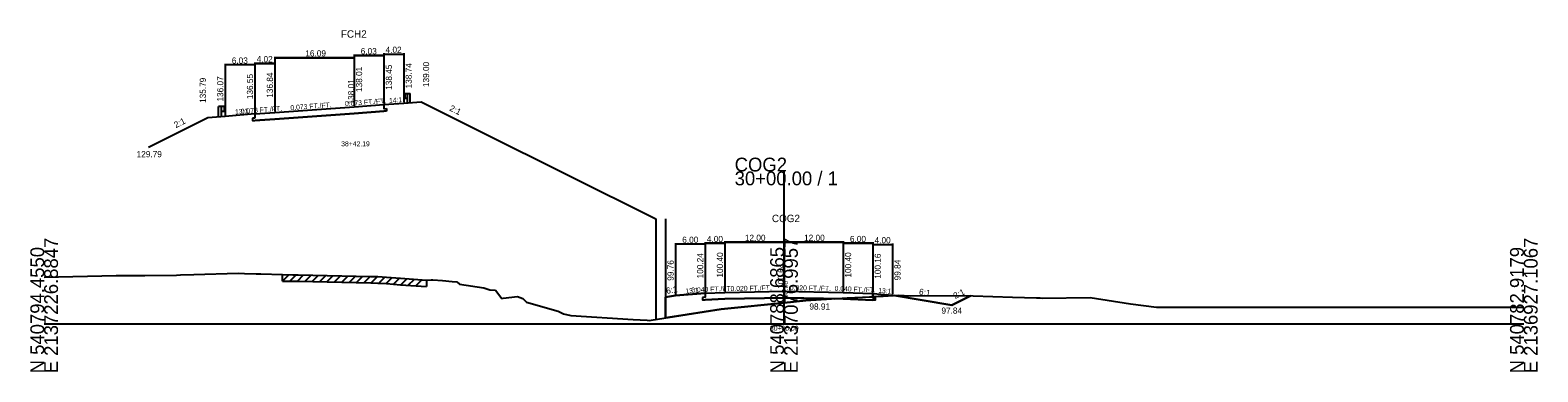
# Model space of a CAD drawing. Extents: x -13397 to 2303, y -10 to 39059.
# Drawn here: x 997.2 to 1302.8, y -9.7 to 59.5 of the extents above; entities that cross this region are included whole.
import ezdxf

# ---------------------------------------------------------------- set-up
doc = ezdxf.new("R2010")
doc.units = 0
for name, color, linetype in [('Level 20', 7, 'Continuous'), ('Level 5', 7, 'Continuous'), ('Level 53', 7, 'Continuous'), ('Level 54', 7, 'Continuous'), ('Level 55', 7, 'Continuous'), ('Level 7', 7, 'Continuous'), ('RD_GPK_XS_Cell', 7, 'Continuous'), ('RD_XS_EwShp', 7, 'Continuous'), ('RD_XS_ExGround', 7, 'Continuous'), ('RD_XS_ExPaveRet', 7, 'Continuous'), ('RD_XS_MedBWall', 7, 'Continuous'), ('RD_XS_Pave', 7, 'Continuous'), ('RD_XS_TX_Baseline', 7, 'Continuous'), ('RD_XS_TX_Elev_EX', 7, 'Continuous'), ('RD_XS_TX_Elev_PR', 7, 'Continuous'), ('RD_XS_TX_Station', 7, 'Continuous')]:
    doc.layers.add(name, color=color, linetype=linetype)

msp = doc.modelspace()

# ---------------------------------------------------------------- linework, layer by layer
at = {"layer": 'Level 20'}
for p, q in [((1036.7, 52.7), (1036.7, 42.27)), ((1042.74, 52.5), (1036.7, 52.5)), ((1042.74, 52.99), (1042.74, 42.75)), ((1042.74, 52.99), (1042.74, 42.75)), ((1042.74, 52.99), (1042.74, 42.75)), ((1042.74, 52.79), (1046.76, 52.79)), ((1042.74, 52.79), (1046.76, 52.79)), ((1046.76, 52.79), (1042.74, 52.79)), ((1042.74, 52.7), (1042.74, 42.75)), ((1046.76, 54.16), (1046.76, 43.04)), ((1046.76, 54.16), (1046.76, 43.04)), ((1046.76, 54.16), (1046.76, 43.04)), ((1046.76, 54.16), (1046.76, 43.04)), ((1046.76, 53.96), (1062.84, 53.96)), ((1046.76, 53.96), (1062.84, 53.96)), ((1062.84, 53.96), (1046.76, 53.96)), ((1062.84, 53.96), (1046.76, 53.96)), ((1046.76, 52.99), (1046.76, 43.04)), ((1046.76, 52.99), (1046.76, 43.04)), ((1046.76, 52.99), (1046.76, 43.04)), ((1062.84, 54.6), (1062.84, 44.21)), ((1062.84, 54.6), (1062.84, 44.21)), ((1062.84, 54.6), (1062.84, 44.21)), ((1062.84, 54.4), (1068.88, 54.4)), ((1068.88, 54.4), (1062.84, 54.4)), ((1068.88, 54.4), (1062.84, 54.4)), ((1062.84, 54.16), (1062.84, 44.21)), ((1062.84, 54.16), (1062.84, 44.21)), ((1062.84, 54.16), (1062.84, 44.21)), ((1062.84, 54.16), (1062.84, 44.21)), ((1068.88, 54.89), (1068.88, 44.65)), ((1068.88, 54.69), (1072.9, 54.69)), ((1068.88, 54.6), (1068.88, 44.65)), ((1068.88, 54.6), (1068.88, 44.65)), ((1068.88, 54.6), (1068.88, 44.65)), ((1072.9, 54.89), (1072.9, 44.94)), ((1072.92, 46.56), (1073.03, 46.65)), ((1072.92, 46.46), (1073.03, 46.37)), ((1072.92, 46.03), (1073.03, 46.12)), ((1072.92, 45.93), (1073.03, 45.84)), ((1073.05, 46.66), (1073.12, 46.67)), ((1073.05, 46.32), (1073.05, 46.17)), ((1073.12, 46.73), (1073.12, 45.76)), ((1073.12, 46.73), (1073.68, 46.73)), ((1073.68, 44.74), (1073.68, 46.73)), ((1073.68, 46.73), (1074.23, 46.73)), ((1074.23, 44.74), (1074.23, 46.73)), ((1035.36, 42.07), (1035.36, 44.06)), ((1035.92, 44.06), (1035.36, 44.06)), ((1035.92, 42.07), (1035.92, 44.06)), ((1036.48, 44.06), (1035.92, 44.06)), ((1036.48, 43.08), (1035.92, 43.08)), ((1036.48, 44.06), (1036.48, 43.08)), ((1036.55, 43.98), (1036.48, 43.99)), ((1036.55, 43.16), (1036.48, 43.14)), ((1036.55, 43.65), (1036.55, 43.49)), ((1036.68, 43.88), (1036.57, 43.98)), ((1036.68, 43.78), (1036.57, 43.69)), ((1036.68, 43.35), (1036.57, 43.45)), ((1036.68, 43.25), (1036.57, 43.16)), ((1042.74, 42.55), (1046.76, 42.84)), ((1046.76, 42.84), (1062.84, 44.01)), ((1062.84, 44.01), (1068.88, 44.45)), ((1068.88, 43.12), (1062.84, 42.68)), ((1062.84, 42.68), (1068.88, 43.12)), ((1062.84, 42.68), (1068.88, 43.12)), ((1068.88, 44.45), (1072.9, 44.74)), ((1068.88, 44.45), (1068.88, 43.62)), ((1068.88, 43.62), (1069.38, 43.65)), ((1069.38, 43.15), (1068.88, 43.12)), ((1069.38, 43.65), (1069.38, 43.15)), ((1072.9, 44.74), (1076.42, 45)), ((1073.05, 45.83), (1073.12, 45.82)), ((1073.12, 45.76), (1073.68, 45.76)), ((1076.42, 45), (1088.48, 39)), ((1033.18, 41.79), (1021.12, 35.79)), ((1036.7, 42.07), (1033.18, 41.79)), ((1042.74, 42.55), (1036.7, 42.07)), ((1042.74, 41.71), (1042.23, 41.68)), ((1042.23, 41.68), (1042.23, 41.18)), ((1042.23, 41.18), (1042.74, 41.21)), ((1042.74, 42.55), (1042.74, 41.71)), ((1046.76, 41.51), (1042.74, 41.21)), ((1046.76, 41.51), (1042.74, 41.21)), ((1042.74, 41.21), (1046.76, 41.51)), ((1062.84, 42.68), (1046.76, 41.51)), ((1062.84, 42.68), (1046.76, 41.51)), ((1046.76, 41.51), (1062.84, 42.68)), ((1046.76, 41.51), (1062.84, 42.68)), ((1088.48, 39), (1124, 21.33))]:
    msp.add_line(p, q, dxfattribs=at)
for centre, radius, start, end in [((1072.96, 46.51), 0.0651, 129.0336, 230.9663), ((1072.96, 45.98), 0.0651, 129.0336, 230.9663), ((1072.99, 46.17), 0.0651, 302.9895, 0), ((1073.05, 46.63), 0.026, 90, 129.0505), ((1072.99, 46.32), 0.0651, 0, 45), ((1036.55, 43.96), 0.026, 50.9495, 90), ((1036.61, 43.65), 0.0651, 135, 180), ((1036.61, 43.49), 0.0651, 180, 237.0105), ((1036.55, 43.18), 0.026, 270, 309.0504), ((1036.64, 43.83), 0.0651, 309.0337, 50.9664), ((1036.64, 43.3), 0.0651, 309.0337, 50.9664), ((1073.05, 45.86), 0.026, 230.9496, 270)]:
    msp.add_arc(centre, radius, start, end, dxfattribs=at)
at = {"layer": 'Level 5'}
for p, q in [((1134, 6.24), (1134, 5.41)), ((1168, 6.16), (1168, 5.33)), ((1134, 5.41), (1133.5, 5.39)), ((1133.5, 5.39), (1133.5, 4.89)), ((1133.5, 4.89), (1134, 4.91)), ((1138, 5.07), (1134, 4.91)), ((1138, 5.07), (1134, 4.91)), ((1138, 5.07), (1134, 4.91)), ((1134, 4.91), (1138, 5.07)), ((1150, 5.31), (1138, 5.07)), ((1150, 5.31), (1138, 5.07)), ((1150, 5.31), (1138, 5.07)), ((1138, 5.07), (1150, 5.31)), ((1138, 5.07), (1150, 5.31)), ((1162, 5.07), (1150, 5.31)), ((1162, 5.07), (1150, 5.31)), ((1150, 5.31), (1162, 5.07)), ((1150, 5.31), (1162, 5.07)), ((1150, 5.31), (1162, 5.07)), ((1168, 4.83), (1162, 5.07)), ((1162, 5.07), (1168, 4.83)), ((1162, 5.07), (1168, 4.83)), ((1162, 5.07), (1168, 4.83)), ((1168, 5.33), (1168.5, 5.31)), ((1168.5, 4.81), (1168, 4.83)), ((1168.5, 5.31), (1168.5, 4.81))]:
    msp.add_line(p, q, dxfattribs=at)
at = {"layer": 'Level 54'}
for p, q in [((1128, 16.39), (1128, 5.96)), ((1134, 16.19), (1128, 16.19)), ((1134, 16.55), (1134, 6.44)), ((1134, 16.55), (1134, 6.44)), ((1134, 16.55), (1134, 6.44)), ((1134, 16.55), (1134, 6.44)), ((1134, 16.39), (1134, 6.44)), ((1134, 16.35), (1138, 16.35)), ((1134, 16.35), (1138, 16.35)), ((1134, 16.35), (1138, 16.35)), ((1138, 16.35), (1134, 16.35)), ((1138, 16.79), (1138, 6.6)), ((1138, 16.79), (1138, 6.6)), ((1138, 16.79), (1138, 6.6)), ((1138, 16.79), (1138, 6.6)), ((1138, 16.79), (1138, 6.6)), ((1138, 16.59), (1150, 16.59)), ((1138, 16.59), (1150, 16.59)), ((1138, 16.59), (1150, 16.59)), ((1150, 16.59), (1138, 16.59)), ((1150, 16.59), (1138, 16.59)), ((1138, 16.55), (1138, 6.6)), ((1138, 16.55), (1138, 6.6)), ((1138, 16.55), (1138, 6.6)), ((1138, 16.55), (1138, 6.6)), ((1150, 16.79), (1150, 6.84)), ((1150, 16.79), (1150, 6.84)), ((1150, 16.79), (1150, 6.84)), ((1150, 16.79), (1150, 6.84)), ((1150, 16.79), (1150, 6.84)), ((1150, 16.79), (1150, 6.84)), ((1150, 16.79), (1150, 6.84)), ((1150, 16.79), (1150, 6.84)), ((1150, 16.79), (1150, 6.84)), ((1150, 16.79), (1150, 6.84)), ((1150, 16.59), (1162, 16.59)), ((1150, 16.59), (1162, 16.59)), ((1162, 16.59), (1150, 16.59)), ((1162, 16.59), (1150, 16.59)), ((1162, 16.59), (1150, 16.59)), ((1162, 16.79), (1162, 6.6)), ((1162, 16.79), (1162, 6.6)), ((1162, 16.79), (1162, 6.6)), ((1162, 16.79), (1162, 6.6)), ((1162, 16.79), (1162, 6.6)), ((1162, 16.55), (1162, 6.6)), ((1162, 16.55), (1162, 6.6)), ((1162, 16.55), (1162, 6.6)), ((1162, 16.55), (1162, 6.6)), ((1162, 16.35), (1168, 16.35)), ((1168, 16.35), (1162, 16.35)), ((1168, 16.35), (1162, 16.35)), ((1168, 16.35), (1162, 16.35)), ((1168, 16.55), (1168, 6.36)), ((1168, 16.55), (1168, 6.36)), ((1168, 16.55), (1168, 6.36)), ((1168, 16.55), (1168, 6.36)), ((1168, 16.31), (1168, 6.36)), ((1168, 16.11), (1172, 16.11)), ((1172, 16.31), (1172, 6.04))]:
    msp.add_line(p, q, dxfattribs=at)
at = {"layer": 'Level 7'}
for p, q in [((1134, 6.24), (1128, 5.76)), ((1168, 6.16), (1172, 5.84)), ((1128, 5.76), (1126, 5.43)), ((1126, 5.43), (1126, 1.24)), ((1172, 5.84), (1184, 3.84)), ((1184, 3.84), (1187.78, 5.73))]:
    msp.add_line(p, q, dxfattribs=at)
at = {"layer": 'RD_GPK_XS_Cell'}
for p, q in [((1150, 0), (1150, 30.9)), ((1000, 0), (1150, 0)), ((1150, 0), (1300, 0))]:
    msp.add_line(p, q, dxfattribs=at)
at = {"layer": 'RD_XS_EwShp'}
for points in [[(1133.5, 5.39), (1133.5, 4.89), (1134, 4.91), (1138, 5.07), (1150, 5.31), (1160.14, 5.1), (1154.45, 4.75), (1150.03, 4.28), (1137.96, 3.04), (1137.24, 2.98), (1130.35, 1.93), (1126, 1.24), (1126, 5.43), (1128, 5.76), (1134, 6.24), (1134, 5.41)], [(1168, 6.16), (1172, 5.84), (1172.43, 5.77), (1170.08, 5.61), (1168, 5.53)], [(1162, 5.07), (1160.14, 5.1), (1162.81, 5.27), (1165.93, 5.45), (1168, 5.53), (1168, 5.33), (1168.5, 5.31), (1168.5, 4.81), (1168, 4.83)], [(1172.43, 5.77), (1173.22, 5.82), (1175.59, 5.73), (1186.32, 5.77), (1187.78, 5.73), (1184, 3.84)]]:
    msp.add_lwpolyline(points, close=True, dxfattribs=at)
at = {"layer": 'RD_XS_ExGround'}
for p, q in [((1000, 9.46), (1014.6, 9.84)), ((1014.6, 9.84), (1020.44, 9.8)), ((1020.44, 9.8), (1026.83, 9.91)), ((1026.83, 9.91), (1027.64, 9.93)), ((1027.64, 9.93), (1030.34, 10.02)), ((1030.34, 10.02), (1039.33, 10.3)), ((1039.33, 10.3), (1040.59, 10.23)), ((1040.59, 10.23), (1042.99, 10.18)), ((1042.99, 10.18), (1043.9, 10.16)), ((1043.9, 10.16), (1048.33, 10.01)), ((1048.33, 10.01), (1050.43, 9.98)), ((1050.43, 9.98), (1051.53, 9.95)), ((1051.53, 9.95), (1066.22, 9.63)), ((1066.22, 9.63), (1067.68, 9.59)), ((1067.68, 9.59), (1069.39, 9.49)), ((1069.39, 9.49), (1072.24, 9.26)), ((1072.24, 9.26), (1077.52, 8.9)), ((1077.52, 8.9), (1078.47, 8.97)), ((1078.47, 8.97), (1078.8, 8.96)), ((1078.8, 8.96), (1080.76, 8.83)), ((1080.76, 8.83), (1082.71, 8.62)), ((1082.71, 8.62), (1083.68, 8.53)), ((1083.68, 8.53), (1084.18, 8.09)), ((1084.18, 8.09), (1089.14, 7.34)), ((1089.14, 7.34), (1090.36, 6.93)), ((1090.36, 6.93), (1091.51, 6.83)), ((1091.51, 6.83), (1092.77, 5.19)), ((1092.77, 5.19), (1093.09, 5.23)), ((1093.09, 5.23), (1095.97, 5.56)), ((1095.97, 5.56), (1097.02, 5.15)), ((1097.02, 5.15), (1097.8, 4.44)), ((1097.8, 4.44), (1104.19, 2.62)), ((1137.96, 3.04), (1150.03, 4.28)), ((1150.03, 4.28), (1154.45, 4.75)), ((1154.45, 4.75), (1162.81, 5.27)), ((1162.81, 5.27), (1165.93, 5.45)), ((1165.93, 5.45), (1170.08, 5.61)), ((1170.08, 5.61), (1173.22, 5.82)), ((1173.22, 5.82), (1175.59, 5.73)), ((1175.59, 5.73), (1186.32, 5.77)), ((1186.32, 5.77), (1188.37, 5.72)), ((1188.37, 5.72), (1196.34, 5.46)), ((1196.34, 5.46), (1201.16, 5.28)), ((1201.16, 5.28), (1201.92, 5.29)), ((1201.92, 5.29), (1202.41, 5.26)), ((1202.41, 5.26), (1212.05, 5.35)), ((1212.05, 5.35), (1220.24, 4.07)), ((1220.24, 4.07), (1225.55, 3.44)), ((1225.55, 3.44), (1231.98, 3.44)), ((1231.98, 3.44), (1300, 3.44)), ((1104.19, 2.62), (1105.3, 2.03)), ((1105.3, 2.03), (1106.78, 1.72)), ((1106.78, 1.72), (1119.44, 0.93)), ((1119.44, 0.93), (1122.29, 0.76)), ((1122.29, 0.76), (1122.66, 0.73)), ((1122.66, 0.73), (1123.07, 0.78)), ((1123.07, 0.78), (1130.35, 1.93)), ((1130.35, 1.93), (1137.24, 2.98)), ((1137.24, 2.98), (1137.96, 3.04))]:
    msp.add_line(p, q, dxfattribs=at)
at = {"layer": 'RD_XS_ExPaveRet'}
for p, q in [((1048.33, 8.71), (1048.33, 10.01)), ((1048.33, 8.71), (1049.62, 9.99)), ((1049.83, 8.69), (1051.11, 9.96)), ((1051.33, 8.66), (1052.61, 9.93)), ((1052.83, 8.62), (1054.11, 9.9)), ((1054.33, 8.59), (1055.61, 9.86)), ((1055.83, 8.56), (1057.11, 9.83)), ((1057.33, 8.53), (1058.61, 9.8)), ((1058.83, 8.49), (1060.11, 9.77)), ((1060.33, 8.46), (1061.61, 9.73)), ((1061.83, 8.43), (1063.11, 9.7)), ((1063.33, 8.39), (1064.61, 9.67)), ((1064.83, 8.36), (1066.11, 9.63)), ((1066.33, 8.33), (1067.6, 9.59)), ((1067.83, 8.28), (1069.06, 9.51)), ((1069.33, 8.19), (1070.54, 9.4)), ((1070.83, 8.07), (1072.04, 9.28)), ((1072.33, 7.96), (1073.55, 9.17)), ((1048.33, 8.71), (1050.43, 8.68)), ((1050.43, 8.68), (1051.53, 8.65)), ((1051.53, 8.65), (1066.22, 8.33)), ((1066.22, 8.33), (1067.68, 8.29)), ((1067.68, 8.29), (1069.39, 8.19)), ((1069.39, 8.19), (1072.24, 7.96)), ((1072.24, 7.96), (1077.52, 7.6)), ((1073.83, 7.85), (1075.05, 9.07)), ((1075.33, 7.75), (1076.55, 8.97)), ((1077.52, 8.9), (1077.52, 7.6))]:
    msp.add_line(p, q, dxfattribs=at)
at = {"layer": 'RD_XS_MedBWall'}
for p, q in [((1124, 21.33), (1124, 0.93)), ((1126, 21.33), (1126, 5.43))]:
    msp.add_line(p, q, dxfattribs=at)
at = {"layer": 'RD_XS_Pave'}
for p, q in [((1134, 6.24), (1138, 6.4)), ((1138, 6.4), (1150, 6.64)), ((1150, 6.64), (1162, 6.4)), ((1162, 6.4), (1168, 6.16))]:
    msp.add_line(p, q, dxfattribs=at)

# ---------------------------------------------------------------- texts
at = {"layer": 'Level 20'}
for s, height, p in [('FCH2', 1.5, (1060.16, 58.01)), ('16.09', 1.25, (1052.95, 54.21)), ('16.09', 1.25, (1052.95, 54.21)), ('16.09', 1.25, (1052.95, 54.21)), ('16.09', 1.25, (1052.95, 54.21)), ('6.03', 1.25, (1064.18, 54.65)), ('6.03', 1.25, (1064.18, 54.65)), ('6.03', 1.25, (1064.18, 54.65)), ('4.02', 1.25, (1069.22, 54.94)), ('6.03', 1.25, (1038.04, 52.75)), ('4.02', 1.25, (1043.08, 53.04)), ('4.02', 1.25, (1043.08, 53.04)), ('4.02', 1.25, (1043.08, 53.04)), ('38+42.19', 1, (1060.22, 36.01)), ('129.79', 1.25, (1018.75, 33.79))]:
    msp.add_text(s, height=height, dxfattribs=at).set_placement(p)
for s, height, rotation, p in [('138.01', 1.25, 90, (1064.47, 47.01)), ('138.01', 1.25, 90, (1064.47, 47.01)), ('138.45', 1.25, 90, (1070.51, 47.45)), ('138.74', 1.25, 90, (1074.53, 47.74)), ('139.00', 1.25, 90, (1078.05, 48)), ('135.79', 1.25, 90, (1032.8, 44.79)), ('136.07', 1.25, 90, (1036.32, 45.07)), ('136.55', 1.25, 90, (1042.35, 45.55)), ('136.84', 1.25, 90, (1046.38, 45.84)), ('136.84', 1.25, 90, (1046.38, 45.84)), (' 138.01', 1.25, 90, (1062.84, 44.01)), ('14:1', 1, 4.1418, (1069.97, 44.78)), ('13:1', 1, 4.5489, (1038.74, 42.48)), ('0.073 FT./FT.', 1, 4.1653, (1039.91, 42.59)), ('0.073 FT./FT.', 1, 4.1653, (1039.91, 42.59)), ('0.073 FT./FT.', 1, 4.1653, (1039.91, 42.59)), ('0.073 FT./FT.', 1, 4.1645, (1049.96, 43.32)), ('0.073 FT./FT.', 1, 4.1645, (1049.96, 43.32)), ('0.073 FT./FT.', 1, 4.1645, (1049.96, 43.32)), ('0.073 FT./FT.', 1, 4.1645, (1049.96, 43.32)), ('0.073 FT./FT.', 1, 4.1636, (1061.02, 44.13)), ('0.073 FT./FT.', 1, 4.1636, (1061.02, 44.13)), ('0.073 FT./FT.', 1, 4.1636, (1061.02, 44.13)), ('2:1', 1.25, 333.5555, (1082.05, 43.31)), ('2:1', 1.25, 26.4389, (1026.7, 39.68))]:
    msp.add_text(s, height=height, rotation=rotation, dxfattribs=at).set_placement(p)
at = {"layer": 'Level 53'}
for s, rotation, p in [('99.76', 90, (1127.62, 8.76)), ('100.24', 90, (1133.62, 9.24)), ('100.40', 90, (1137.63, 9.4)), ('100.40', 90, (1137.63, 9.4)), ('100.40', 90, (1137.63, 9.4)), ('100.40', 90, (1163.62, 9.4)), ('100.40', 90, (1163.62, 9.4)), ('100.40', 90, (1163.62, 9.4)), ('100.16', 90, (1169.63, 9.16)), ('99.84', 90, (1173.63, 8.84)), ('6:1', 9.4623, (1126.21, 6.09)), ('6:1', 350.5377, (1177.3, 5.97))]:
    msp.add_text(s, height=1.25, rotation=rotation, dxfattribs=at).set_placement(p)
for s, p in [('98.91', (1155.15, 2.91)), ('97.84', (1181.92, 2.09))]:
    msp.add_text(s, height=1.25, dxfattribs=at).set_placement(p)
at = {"layer": 'Level 54'}
for s, p in [('6.00', (1129.37, 16.44)), ('4.00', (1134.37, 16.6)), ('4.00', (1134.37, 16.6)), ('4.00', (1134.37, 16.6)), ('4.00', (1134.37, 16.6)), ('12.00', (1142.07, 16.84)), ('12.00', (1142.07, 16.84)), ('12.00', (1142.07, 16.84)), ('12.00', (1142.07, 16.84)), ('12.00', (1142.07, 16.84)), ('12.00', (1154.07, 16.84)), ('12.00', (1154.07, 16.84)), ('12.00', (1154.07, 16.84)), ('12.00', (1154.07, 16.84)), ('12.00', (1154.07, 16.84)), ('6.00', (1163.37, 16.6)), ('6.00', (1163.37, 16.6)), ('6.00', (1163.37, 16.6)), ('6.00', (1163.37, 16.6)), ('4.00', (1168.37, 16.36))]:
    msp.add_text(s, height=1.25, dxfattribs=at).set_placement(p)
at = {"layer": 'Level 55'}
for s, height, rotation, p in [('13:1', 1, 4.5739, (1130.03, 6.17)), ('0.040 FT./FT.', 1, 2.2906, (1131.22, 6.38)), ('0.040 FT./FT.', 1, 2.2906, (1131.22, 6.38)), ('0.040 FT./FT.', 1, 2.2906, (1131.22, 6.38)), ('0.040 FT./FT.', 1, 2.2906, (1131.22, 6.38)), ('0.020 FT./FT.', 1, 1.1458, (1139.17, 6.67)), ('0.020 FT./FT.', 1, 1.1458, (1139.17, 6.67)), ('0.020 FT./FT.', 1, 1.1458, (1139.17, 6.67)), ('0.020 FT./FT.', 1, 1.1458, (1139.17, 6.67)), ('0.020 FT./FT.', 1, 1.1458, (1139.17, 6.67)), ('0.020 FT./FT.', 1, 358.8542, (1151.18, 6.87)), ('0.020 FT./FT.', 1, 358.8542, (1151.18, 6.87)), ('0.020 FT./FT.', 1, 358.8542, (1151.18, 6.87)), ('0.020 FT./FT.', 1, 358.8542, (1151.18, 6.87)), ('0.020 FT./FT.', 1, 358.8542, (1151.18, 6.87)), ('0.040 FT./FT.', 1, 357.7094, (1160.24, 6.72)), ('0.040 FT./FT.', 1, 357.7094, (1160.24, 6.72)), ('0.040 FT./FT.', 1, 357.7094, (1160.24, 6.72)), ('0.040 FT./FT.', 1, 357.7094, (1160.24, 6.72)), ('13:1', 1, 355.4261, (1169.07, 6.33)), ('2:1', 1.25, 26.5651, (1184.71, 5.04))]:
    msp.add_text(s, height=height, rotation=rotation, dxfattribs=at).set_placement(p)
at = {"layer": 'RD_GPK_XS_Cell'}
for s, p in [('COG2', (1140, 30.9)), ('30+00.00 / 1', (1140, 28.1))]:
    msp.add_text(s, height=2.8, dxfattribs=at).set_placement(p)
for s, p in [('N 540794.4550', (1000, -10)), ('E 2137226.8847', (1002.8, -10)), ('N 540788.6865', (1150, -10)), ('E 2137076.9957', (1152.8, -10)), ('N 540782.9179', (1300, -10)), ('E 2136927.1067', (1302.8, -10))]:
    msp.add_text(s, height=2.8, rotation=90, dxfattribs=at).set_placement(p)
at = {"layer": 'RD_XS_TX_Baseline'}
msp.add_text('COG2', height=1.5, dxfattribs=at).set_placement((1147.55, 20.64))
at = {"layer": 'RD_XS_TX_Elev_EX'}
msp.add_text('98.28', height=1, rotation=90, dxfattribs=at).set_placement((1150.75, 5.28))
at = {"layer": 'RD_XS_TX_Elev_PR'}
msp.add_text(' 100.64', height=1.25, rotation=90, dxfattribs=at).set_placement((1150, 6.64))
at = {"layer": 'RD_XS_TX_Station'}
msp.add_text('30+00.00', height=1, dxfattribs=at).set_placement((1147.15, -1.36))

doc.saveas('drawing.dxf')
